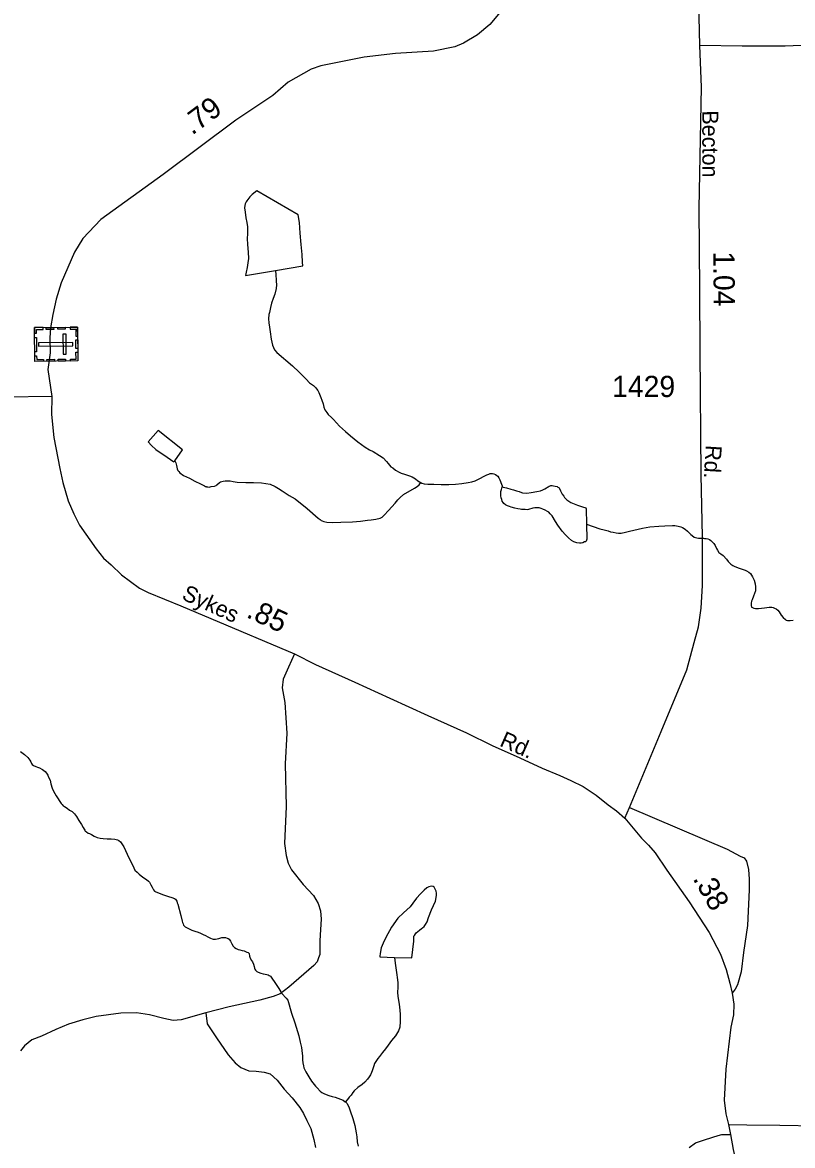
# Model space of a CAD drawing. Extents: x 2220236 to 2384410, y 720751 to 894131.
# Drawn here: x 2288550 to 2293089, y 826230 to 832849 of the extents above; entities that cross this region are included whole.
import ezdxf

# ---------------------------------------------------------------- set-up
doc = ezdxf.new("R2010")
doc.units = 0
for name, color, linetype in [('Exist Cultural Cemetery CELL', 7, 'Continuous'), ('Exist Hydrographic Creek Single Shore', 7, 'Continuous'), ('Exist Hydrographic Misc Water Feature', 7, 'Continuous'), ('Exist Hydrographic Pond Under 1500 Sq Ft', 7, 'Continuous'), ('Exist Road Non-System Type 51', 7, 'Continuous'), ('Exist Road Secondary Mileage Hundredths English Label', 7, 'Continuous'), ('Exist Road Secondary Type 51 Attributed', 7, 'Continuous'), ('Exist Road Secondary Type 51 Label', 7, 'Continuous'), ('Exist Road Secondary Type 51 Number Label', 7, 'Continuous')]:
    doc.layers.add(name, color=color, linetype=linetype)

msp = doc.modelspace()

# ---------------------------------------------------------------- linework, layer by layer
at = {"layer": 'Exist Cultural Cemetery CELL'}
for points in [[(2288875.5, 831053.2), (2288877.3, 830854.1), (2288622.7, 830851.8), (2288620.8, 831050.9)], [(2288621.2, 831017.8), (2288632.7, 831017.9), (2288632.5, 831039.9), (2288672.9, 831040.3), (2288672.8, 831051.4), (2288620.9, 831050.9)], [(2288690.8, 831051.6), (2288734.1, 831052), (2288734.2, 831040.6), (2288690.9, 831040.2)], [(2288758, 831052.2), (2288801.3, 831052.6), (2288801.4, 831041.2), (2288758.1, 831040.8)], [(2288807.8, 831011.8), (2288789.1, 831011.6), (2288790.2, 830893.9), (2288808.8, 830894)], [(2288832.1, 831052.8), (2288832.2, 831041.5), (2288864.4, 831041.8), (2288864.8, 831001.2), (2288875.9, 831001.3), (2288875.5, 831053.2)], [(2288632.8, 830993.5), (2288633.6, 830908.7), (2288622.2, 830908.6), (2288621.4, 830993.4)], [(2288847.1, 830943.9), (2288847, 830962.6), (2288644.2, 830960.8), (2288644.4, 830942.1)], [(2288876.1, 830979.1), (2288876.6, 830927.3), (2288865.2, 830927.2), (2288864.7, 830979)], [(2288622.3, 830884.9), (2288633.8, 830885), (2288634, 830863), (2288674.4, 830863.4), (2288674.5, 830852.3), (2288622.7, 830851.8)], [(2288833.9, 830853.7), (2288833.8, 830865), (2288866, 830865.3), (2288865.6, 830905.9), (2288876.7, 830906), (2288877.2, 830854.1)], [(2288694.8, 830863.8), (2288738.1, 830864.2), (2288738.2, 830852.8), (2288694.9, 830852.5)], [(2288760.7, 830864.4), (2288804, 830864.8), (2288804.1, 830853.4), (2288760.8, 830853)]]:
    msp.add_lwpolyline(points, close=True, dxfattribs=at)
at = {"layer": 'Exist Hydrographic Creek Single Shore'}
for points in [[(2288539.1, 828552.5), (2288561.4, 828535), (2288581.3, 828517.2), (2288593.8, 828501.5), (2288599.5, 828491.6), (2288603.9, 828481.6), (2288607.4, 828476.6), (2288615.8, 828469.9), (2288629.8, 828463.7), (2288639.8, 828459.6), (2288649.9, 828456.1), (2288664.2, 828447.6), (2288668.1, 828445.9), (2288676.2, 828439.8), (2288684.2, 828434), (2288692.2, 828424), (2288700.2, 828412.4), (2288704.6, 828401.5), (2288712.7, 828382.6), (2288716.9, 828361.9), (2288725.2, 828336.4), (2288733.3, 828318.2), (2288749.5, 828290.7), (2288777.8, 828246.8), (2288783.5, 828239.1), (2288789.9, 828232.4), (2288798, 828227.4), (2288813.3, 828218.2), (2288828.1, 828207.1), (2288842.4, 828197.9), (2288856.2, 828184.5), (2288868.3, 828169.5), (2288882.6, 828146.2), (2288897.9, 828122), (2288907.7, 828104.7), (2288913.3, 828093.8), (2288917.2, 828088.1), (2288920.3, 828083.8), (2288922, 828082.1), (2288927.4, 828078.1), (2288937.5, 828071.9), (2288945.3, 828068.5), (2288957.6, 828062.7), (2288972.2, 828054.2), (2288989.8, 828046.3), (2289007.7, 828042.6), (2289025.7, 828040.6), (2289049.3, 828037.8), (2289073.5, 828037.3), (2289094.8, 828035.2), (2289109.5, 828031.6), (2289119.2, 828027.2), (2289127.6, 828019.8), (2289148, 827990.5), (2289176.5, 827926), (2289192.9, 827896.1), (2289207.1, 827866.3), (2289213, 827853), (2289225.3, 827840.7), (2289237.5, 827828.9), (2289259.4, 827811.1), (2289281.8, 827797.5), (2289293.7, 827789.1), (2289299.8, 827781.7), (2289306, 827765.8)], [(2289306, 827765.8), (2289313.9, 827751.9), (2289322.2, 827737.6), (2289328.2, 827729.3), (2289336.4, 827725.9), (2289352.3, 827719.9), (2289376.4, 827710.3), (2289416.8, 827696.3), (2289424.6, 827694.5), (2289430.8, 827692.7), (2289446.7, 827686.8), (2289452.5, 827682.4), (2289460.5, 827670.8), (2289462.9, 827660.9), (2289465, 827652.7), (2289483.4, 827586.7), (2289491.8, 827553.1), (2289494, 827545.5), (2289496.4, 827536.6), (2289499.9, 827529), (2289509.2, 827518.9), (2289524.1, 827511.4), (2289548.1, 827499.4), (2289566.4, 827494.1), (2289584.9, 827487.8), (2289600.2, 827481.9), (2289614.5, 827474.1), (2289628.5, 827468.2), (2289642.4, 827460.4), (2289658.7, 827452.8), (2289668.4, 827448.4), (2289674.6, 827446.6), (2289680.5, 827446.5), (2289688.7, 827447.3), (2289706.8, 827450.9), (2289724.7, 827455.4), (2289735.5, 827456.2), (2289746.6, 827455.9), (2289756.7, 827453.1), (2289763.2, 827449.7), (2289768.7, 827445.6), (2289772.9, 827440.6), (2289776.7, 827434), (2289784.9, 827418.1), (2289792.8, 827404.2), (2289799.2, 827398.1), (2289809.9, 827390.7), (2289821.3, 827386.2), (2289831.1, 827384.3), (2289845.1, 827380.1), (2289857.2, 827376.6), (2289873.1, 827370.3), (2289879.6, 827368.6), (2289885.4, 827361.2), (2289887.4, 827346.4), (2289891.7, 827334.9), (2289899.6, 827320.6), (2289905.7, 827313.3), (2289912, 827299), (2289915.9, 827285.2), (2289918, 827275.3), (2289920.2, 827268.7), (2289922.7, 827264.4), (2289926.3, 827261), (2289931.7, 827256), (2289936.3, 827253.6), (2289948.3, 827247.4), (2289954.5, 827245), (2289967.9, 827242.1), (2289980.3, 827239.6), (2289990.4, 827237.7), (2289998.6, 827235.9), (2290005, 827232.5), (2290011.2, 827228.1), (2290016.6, 827221.4), (2290040.8, 827185.8), (2290061.2, 827156.5), (2290079.6, 827126.6), (2290103.6, 827098.3), (2290113.9, 827085.9), (2290136.6, 827010.7), (2290155, 826952.9), (2290179.7, 826876.9), (2290187.8, 826839), (2290194.3, 826807.7), (2290198.6, 826773.2), (2290200.9, 826757.8), (2290201, 826735.5), (2290203.3, 826717.4), (2290207.2, 826699.2), (2290209.2, 826687.7), (2290219.6, 826663.9), (2290237.6, 826634), (2290253.9, 826609.7), (2290278.2, 826579.7), (2290286.5, 826569.7), (2290304.5, 826550.6)], [(2290304.5, 826550.6), (2290314.5, 826542.2), (2290326.8, 826536.1), (2290340.5, 826530.9), (2290356.7, 826524.9), (2290374.7, 826518.7), (2290393.9, 826514.3), (2290408.9, 826509.1), (2290424.9, 826503.8), (2290440.1, 826497), (2290452.7, 826487.5), (2290453.7, 826486.9)], [(2290453.7, 826486.9), (2290461.1, 826480.1), (2290473.1, 826457.6), (2290481.5, 826433.8), (2290497.9, 826389.8), (2290508.2, 826348), (2290516.8, 826305.8), (2290520.9, 826280.5), (2290523.3, 826252.5), (2290529.3, 826226.2)]]:
    msp.add_lwpolyline(points, dxfattribs=at)
at = {"layer": 'Exist Hydrographic Misc Water Feature'}
for points in [[(2290040.7, 831387.3), (2290042.8, 831362.7), (2290043.9, 831353.5), (2290045.2, 831338.7), (2290046.2, 831323.9), (2290046.5, 831302.6), (2290045.7, 831281.3), (2290037.1, 831247), (2290028.1, 831222.6), (2290018.7, 831195.9), (2290012.5, 831168.8), (2290007, 831140.4), (2290003.2, 831129), (2290000, 831101.8), (2290001.8, 831078.8), (2290005.6, 831054.2), (2290009.9, 831026.2), (2290016.2, 830982.8), (2290024.6, 830946.5), (2290035.6, 830920.7), (2290049, 830905), (2290141.5, 830826), (2290180.4, 830787.5), (2290204.5, 830764), (2290222.2, 830746.3), (2290242.8, 830726.2), (2290264.7, 830708.7), (2290276.6, 830697.6), (2290283, 830690.9), (2290291, 830679.3), (2290297.4, 830669.3), (2290309.2, 830638.9), (2290315.4, 830623), (2290321.5, 830601.6), (2290326, 830581.1), (2290332.3, 830566.9), (2290344.1, 830549.6), (2290352.1, 830539.6), (2290372.4, 830521.8), (2290382.6, 830510.1), (2290400.6, 830490), (2290418.8, 830470), (2290453.3, 830438.1), (2290483.3, 830412.9), (2290525.8, 830376.9), (2290569.8, 830345.5), (2290595.4, 830331.2), (2290618.1, 830319.9), (2290654.4, 830297.8), (2290676.4, 830282.6), (2290696.6, 830262.5), (2290704.6, 830250.9), (2290712.9, 830240.9), (2290721.5, 830230.8), (2290732.9, 830223.4), (2290749, 830211.6), (2290769.7, 830198.7), (2290783.1, 830193.5), (2290801, 830187.5), (2290831.6, 830177.7), (2290847.2, 830171.8), (2290867.3, 830159.9), (2290880.9, 830148.2), (2290889.6, 830142.1), (2290898.7, 830137)], [(2289448, 830265.4), (2289453.4, 830253.2), (2289457.3, 830239), (2289459.7, 830227.5), (2289461.5, 830218.6), (2289465.6, 830209.3), (2289471, 830202), (2289477.7, 830195.3), (2289500.1, 830180.1), (2289534.2, 830163.6), (2289565.9, 830146.6), (2289600.4, 830130.4), (2289614.3, 830122.6), (2289622.4, 830119.1), (2289628.3, 830115.1), (2289632.5, 830113.4), (2289635.7, 830111.7), (2289642.3, 830111.5), (2289651.1, 830111.3), (2289662.3, 830113.4), (2289682.4, 830117.2), (2289691, 830120.3), (2289696.3, 830123.5), (2289712.4, 830137.9), (2289717.7, 830141.1), (2289732.2, 830145.7), (2289744.1, 830147.8), (2289750.3, 830147.7), (2289774.2, 830148.1), (2289792.2, 830144.5), (2289816.1, 830140.7), (2289866.2, 830137.1), (2289912.1, 830137.7), (2289958.3, 830136.1), (2290010, 830128.5), (2290040.2, 830114.8), (2290058.3, 830102.9), (2290080.3, 830089.3), (2290122.7, 830061.2), (2290156.8, 830041.8), (2290227.4, 829984.6), (2290293.8, 829928.1), (2290303.8, 829919.1), (2290309.9, 829914.7), (2290316.1, 829911.3), (2290325.8, 829907.1), (2290344.1, 829903.5), (2290376.2, 829901.8), (2290425.8, 829904.1), (2290495.7, 829906.9), (2290542.7, 829910.8), (2290583.8, 829915.5), (2290604.8, 829917.7), (2290632.5, 829922.7), (2290657.5, 829928.1), (2290662.8, 829929.6), (2290669.5, 829934.4), (2290681.2, 829944.7), (2290707, 829973), (2290746.9, 830017.1), (2290762.7, 830034.8), (2290776.5, 830049.3), (2290796.5, 830067.9), (2290859.9, 830104.3), (2290875.9, 830114.5), (2290888.2, 830125), (2290898.7, 830137)], [(2290898.7, 830137), (2290903.5, 830134.6), (2290916.9, 830130), (2290939.8, 830127.3), (2290975.5, 830127.2), (2291017.5, 830125.6), (2291063.7, 830126.3), (2291101.5, 830127.8), (2291139.6, 830133), (2291177.8, 830138.7), (2291197.9, 830142.2), (2291217.4, 830147.7), (2291245.2, 830161.9), (2291271.1, 830176.1), (2291287, 830184), (2291298.9, 830187.7), (2291306.5, 830190.2), (2291313.4, 830190.7), (2291320.9, 830190.5), (2291329.1, 830188.7), (2291338.5, 830185.2), (2291346.9, 830180.1), (2291351.1, 830176.1), (2291356.8, 830166.2), (2291363.1, 830154.6), (2291373.4, 830128.8), (2291376.5, 830118.2), (2291377.7, 830113.3)], [(2291874.6, 829891.4), (2291953.7, 829865.8), (2291977.8, 829858.1), (2292001.7, 829852.7), (2292015.7, 829848.1), (2292031.7, 829844.5), (2292049.6, 829840.9), (2292063.7, 829838.9), (2292079.5, 829839.6), (2292103.9, 829845.7), (2292127.6, 829851.7), (2292205.3, 829868.1), (2292247.5, 829877.1), (2292301.4, 829880.9), (2292335.2, 829883.5), (2292380.5, 829884.9), (2292395.2, 829883.9), (2292415.2, 829880.2), (2292431.2, 829876.6), (2292439.3, 829872.2), (2292456.4, 829862), (2292469.3, 829850.2), (2292479.6, 829841.1), (2292489.3, 829831.8), (2292497.7, 829825), (2292509.6, 829816.6), (2292516.1, 829814.1), (2292523.9, 829811.4), (2292533.7, 829809.5), (2292545.9, 829809.3), (2292563.9, 829809.9), (2292570.8, 829808.8), (2292576, 829808), (2292580, 829807.9), (2292588.8, 829805.1), (2292599.8, 829801.6), (2292607.9, 829795.8), (2292616, 829788.1), (2292624.3, 829778.1), (2292632.2, 829765.8), (2292640.4, 829749.9), (2292646.4, 829738.3), (2292654.4, 829726), (2292666.6, 829716.6), (2292679.9, 829707.4), (2292699.1, 829686.4), (2292709, 829673), (2292725.1, 829657.3), (2292736.4, 829649.5), (2292749.4, 829642.7), (2292773.5, 829633.3), (2292791.4, 829627.1), (2292809.3, 829621.8), (2292817.4, 829617.7), (2292831.3, 829609.8), (2292841.3, 829601.4), (2292853.7, 829582.5), (2292861.9, 829562.6), (2292868.3, 829540.2), (2292871.2, 829522.1), (2292871.3, 829510), (2292870.4, 829500.1), (2292864.8, 829483.9), (2292858.6, 829468.2), (2292849.9, 829447.1), (2292847.1, 829438.3), (2292844.9, 829425.9), (2292844.7, 829417), (2292845.3, 829410.5), (2292846.1, 829406.2), (2292847.4, 829403.9), (2292852.9, 829401.1), (2292861.4, 829397.7), (2292871.2, 829395.8), (2292888.9, 829395.5), (2292905.3, 829396.8), (2292923.4, 829399), (2292937.9, 829401), (2292951.4, 829402.4), (2292967.4, 829403), (2292975.3, 829401.2), (2292982.7, 829397.8), (2292991.5, 829393.3), (2293001.5, 829385.9), (2293009.5, 829375.9), (2293021.6, 829356.6), (2293034.1, 829341.6), (2293047.9, 829329.8), (2293051.5, 829327.5), (2293058.3, 829324), (2293061.9, 829324), (2293075.7, 829324.3), (2293091.8, 829326.6)], [(2290743.3, 827339.2), (2290747.5, 827304.7), (2290756.2, 827236.6), (2290758.2, 827220.8), (2290762.5, 827190.5), (2290762.5, 827161), (2290761, 827134.8), (2290763.1, 827108.5), (2290769.3, 827074.6), (2290771.7, 827048.3), (2290776, 827004.9), (2290776.7, 826960.7), (2290775, 826926.9), (2290767.1, 826905.1), (2290748.4, 826876), (2290725.9, 826848.6), (2290706, 826821.7), (2290690.1, 826800.1), (2290672.2, 826777.5), (2290654.4, 826755.6), (2290644.7, 826743.6), (2290632.5, 826725.9), (2290625, 826713.5), (2290621.1, 826698.9), (2290611.3, 826671.2), (2290607.5, 826661.4), (2290601.3, 826646.8), (2290593.5, 826634.8), (2290583.7, 826620.9), (2290567.9, 826602.6), (2290552.2, 826588.8), (2290526, 826572.3), (2290504.2, 826552.1), (2290496.5, 826542.4), (2290486.7, 826527.8), (2290476.6, 826515.9), (2290470.9, 826510.1), (2290453.7, 826486.9)]]:
    msp.add_lwpolyline(points, dxfattribs=at)
at = {"layer": 'Exist Hydrographic Pond Under 1500 Sq Ft'}
for points in [[(2290040.7, 831387.3), (2290202.3, 831414.2), (2290200.1, 831436.5), (2290197.8, 831482.5), (2290193.1, 831540.6), (2290186.6, 831608), (2290182, 831670.4), (2290175.7, 831716.5), (2289932.4, 831857.6), (2289904.7, 831836.2), (2289890.9, 831821.7), (2289878.8, 831805.6), (2289873.1, 831797.5), (2289869, 831791.7), (2289863.2, 831779.7), (2289860, 831769.9), (2289859.4, 831757.4), (2289861.8, 831731.2), (2289866.1, 831697.6), (2289872.1, 831671.3), (2289875.8, 831644), (2289876.6, 831622), (2289876.9, 831603.9), (2289875, 831575.1), (2289877.5, 831539.9), (2289881.2, 831495.6), (2289882.1, 831457.9), (2289878.6, 831431.7), (2289874.8, 831405.5), (2289868, 831378.4), (2289865.3, 831358.2), (2290040.7, 831387.3)], [(2289448, 830265.4), (2289492.7, 830330.1), (2289349.7, 830444.6), (2289292, 830377.9), (2289310.5, 830356.2), (2289336.6, 830332.7), (2289403.2, 830287), (2289443, 830259), (2289448, 830265.4)], [(2291874.6, 829891.4), (2291876, 829803.5), (2291872.5, 829793.1), (2291868.5, 829788.9), (2291862.6, 829787.4), (2291852.3, 829782.6), (2291842.4, 829781.2), (2291833.2, 829779.8), (2291817.5, 829781.7), (2291799.9, 829788), (2291786.3, 829796.5), (2291768, 829812.3), (2291751.3, 829830), (2291731.7, 829851.7), (2291705.6, 829887.4), (2291691.2, 829907.3), (2291671.3, 829941.5), (2291660.7, 829953.9), (2291652, 829962.3), (2291644.9, 829967.3), (2291630.6, 829975.2), (2291617.6, 829981), (2291606.6, 829984.5), (2291595.5, 829988), (2291582.1, 829989.3), (2291570.9, 829988.6), (2291558.7, 829986.5), (2291533, 829977.9), (2291525.4, 829977.4), (2291513, 829978.3), (2291501.5, 829978.5), (2291491, 829979.7), (2291482.8, 829980.5), (2291468.8, 829983.5), (2291452.5, 829987.1), (2291430.6, 829993.1), (2291420.2, 829996.6), (2291408.5, 830001.1), (2291396.5, 830006.9), (2291386.5, 830014.7), (2291382.6, 830020.3), (2291378.2, 830028.6), (2291375.1, 830037.9), (2291372.1, 830048.4), (2291370.3, 830059.3), (2291369, 830074.1), (2291370.2, 830085.5), (2291373.4, 830096.9), (2291377.7, 830113.3)], [(2291377.7, 830113.3), (2291383.5, 830110.5), (2291403.5, 830106.8), (2291427.6, 830099.1), (2291443.5, 830093.9), (2291461.8, 830089.2), (2291477.8, 830084), (2291492.1, 830079.7), (2291498, 830078), (2291521.9, 830075.8), (2291547.8, 830078.6), (2291581.7, 830084.4), (2291603.8, 830088.9), (2291617.4, 830094.2), (2291629.7, 830101.5), (2291639.6, 830106.8), (2291645.3, 830111), (2291648.6, 830112.6), (2291653.6, 830115.7), (2291661.2, 830118.9), (2291663.5, 830119.5), (2291671.3, 830119.3), (2291680.2, 830119.1), (2291690.3, 830116.6), (2291701.4, 830113.8), (2291705.9, 830111.4), (2291710.8, 830108.6), (2291712.4, 830107), (2291713.7, 830106.3), (2291721.9, 830088.1), (2291731.7, 830069.8), (2291739.9, 830056.5), (2291745, 830048.9), (2291750.5, 830043.2), (2291758.8, 830035.5), (2291769.8, 830028.1), (2291782.1, 830020.3), (2291820.5, 830004.7), (2291850.5, 829995.2), (2291870.4, 829988.9), (2291872.5, 829983.3), (2291874.6, 829891.4)], [(2290743.3, 827339.2), (2290845.2, 827335.4), (2290856.1, 827433.6), (2290856.3, 827445.1), (2290855.9, 827457.6), (2290857.7, 827463.1), (2290860, 827467.3), (2290865.8, 827477.7), (2290871.5, 827483.5), (2290879.6, 827491.5), (2290889.6, 827500.1), (2290901.3, 827509.7), (2290907.6, 827513.9), (2290916.9, 827521.9), (2290925.3, 827532.2), (2290935.2, 827548.4), (2290943, 827574.5), (2290960.6, 827620), (2290984, 827670.4), (2290988, 827691), (2290989.6, 827704.7), (2290989.9, 827717.2), (2290987.5, 827728.7), (2290985.3, 827736.9), (2290981.3, 827745.2), (2290977.1, 827752.5), (2290971, 827756.9), (2290959.2, 827758.8), (2290945.4, 827754.2), (2290933.4, 827748.5), (2290917.1, 827735.7), (2290895.7, 827714.2), (2290871.8, 827687.5), (2290850.3, 827659.4), (2290834.4, 827637.4), (2290796.6, 827601.5), (2290762.8, 827571), (2290725.6, 827516.7), (2290692.2, 827456), (2290676.4, 827421.9), (2290664.7, 827394.3), (2290658.8, 827361.6), (2290657.1, 827345.9), (2290657.1, 827342), (2290743.3, 827339.2)]]:
    msp.add_lwpolyline(points, dxfattribs=at)
at = {"layer": 'Exist Road Non-System Type 51'}
for points in [[(2293279.6, 832719), (2293044.3, 832710.2), (2292791.4, 832710.2), (2292542.1, 832713.7)], [(2290153.9, 829128.9), (2290118.9, 829050.1), (2290087.4, 828978.3), (2290080.4, 828927.5), (2290096.1, 828841.7), (2290108.4, 828661.4), (2290097.9, 828479.3), (2290104.9, 828228.9), (2290094.4, 828010), (2290104.9, 827940), (2290117.1, 827894.4), (2290136.4, 827854.2), (2290204.6, 827768.4), (2290265.9, 827703.6), (2290293.9, 827656.3), (2290306.1, 827612.5), (2290311.4, 827563.5), (2290306.1, 827504), (2290302.6, 827437.4), (2290302.6, 827377.9), (2290302.6, 827356.9), (2290295.6, 827335.9), (2290286.9, 827313.1), (2290267.6, 827292.1), (2290119.7, 827162.5), (2290069, 827124), (2290027, 827108.2), (2289948.3, 827087.2), (2289768, 827047), (2289631.5, 827011.9)], [(2292127.7, 828222.7), (2292703.6, 827976.7), (2292780.9, 827936.3), (2292803.7, 827925.8), (2292817.8, 827906.4), (2292828.3, 827857.2), (2292833.6, 827799.3), (2292833.6, 827737.8), (2292823.9, 827526.9), (2292800.2, 827367), (2292786.1, 827254.6), (2292765.1, 827177.3), (2292751, 827150.9), (2292733.5, 827128.1)], [(2289631.5, 827011.9), (2289485.8, 826971), (2289437.9, 826966.6), (2289383.8, 826977.9), (2289299.7, 827001.2), (2289221.5, 827012.5), (2289129.7, 827009.6), (2288983.9, 826990.2), (2288906.2, 826971.4), (2288822.4, 826944.8), (2288746.6, 826913.9), (2288663, 826875.3), (2288605.4, 826852.7), (2288561.7, 826818.4), (2288538.1, 826788.1)], [(2289631.5, 827011.9), (2289638.5, 826947.2), (2289694.5, 826864.9), (2289762.8, 826765.1), (2289804.8, 826717.8), (2289838, 826689.8), (2289885.3, 826670.5), (2289927.3, 826668.8), (2289974.5, 826661.7), (2290009.5, 826653), (2290051.5, 826616.2), (2290093.5, 826561.9), (2290140.7, 826511.2), (2290184.5, 826455.1), (2290207.2, 826418.4), (2290226.5, 826378.1), (2290249.2, 826330.8), (2290266.7, 826266), (2290277.2, 826218.7)], [(2292480.3, 826218.7), (2292517.1, 826245), (2292563.4, 826262.5), (2292619.4, 826280), (2292650.9, 826288.8), (2292671.9, 826295.8), (2292696.4, 826295.8), (2292722.9, 826294.1)]]:
    msp.add_lwpolyline(points, dxfattribs=at)
at = {"layer": 'Exist Road Secondary Type 51 Attributed'}
for points in [[(2292099.6, 828159.4), (2292127.7, 828222.7), (2292314.7, 828670.7), (2292465.7, 829034.5), (2292509.6, 829194.3), (2292534.2, 829287.5), (2292550, 829398.2), (2292558.8, 829529.9), (2292558.8, 829818.1), (2292550, 830183.6), (2292544.7, 830909.2), (2292543, 831272.9), (2292538.6, 831754.4), (2292551.7, 832467.7), (2292542.1, 832713.7), (2292533.3, 833135.4), (2292528, 833486.8), (2292522.8, 833574.7)], [(2291365.3, 832910.2), (2291304, 832837.6), (2291232.5, 832776.9), (2291149, 832728.3), (2291099.3, 832705.7), (2290973.6, 832680.5), (2290747.8, 832666.4), (2290564.2, 832644.9), (2290308.6, 832594.4), (2290250.8, 832574), (2290115.6, 832496.6), (2290026.4, 832419.9), (2289807.9, 832273.8), (2289379.1, 831954), (2289011.7, 831688.5), (2288906.8, 831575.7), (2288857.5, 831495.2), (2288777.4, 831314.5), (2288748.2, 831218.3), (2288729.2, 831128.1), (2288715.9, 831050), (2288712.5, 830990.1), (2288713.3, 830902.1), (2288700.2, 830804), (2288722.5, 830645.8)], [(2288722.5, 830645.8), (2288166.6, 830636.5), (2287886.3, 830636.5), (2287733.4, 830634.2), (2287668.5, 830622.6), (2287615.3, 830608.7), (2287527.2, 830569.3), (2287464.7, 830529.9), (2287392.9, 830471.9), (2287212.2, 830293.5), (2287021.1, 830132.4), (2286932, 830065.7), (2286522.9, 829770), (2286284.5, 829603.8), (2286114.3, 829486.9), (2285938.2, 829361.7)], [(2288722.5, 830645.8), (2288720.7, 830538.2), (2288735.9, 830402.5), (2288769.7, 830220.9), (2288788.4, 830137.1), (2288819.3, 830029.5), (2288852.1, 829953.8), (2288886.7, 829886.1), (2288984, 829747.1), (2289028.4, 829691.6), (2289072.8, 829651.9), (2289133.4, 829594.5), (2289240.1, 829515.7), (2289290.2, 829490), (2289482.9, 829411.9), (2289659.5, 829335.6), (2290153.9, 829128.9), (2290276.4, 829065.8), (2290509.1, 828960.8), (2290715.6, 828866.2), (2290939.6, 828764.7), (2291167, 828663.1), (2291317.5, 828587.8), (2291482, 828514.3), (2291613.3, 828454.7), (2291716.8, 828410.7), (2291783, 828381.2), (2291855.5, 828345.7), (2291931, 828294.7), (2292003, 828238.5), (2292050.4, 828203.4), (2292099.6, 828159.4)], [(2292099.6, 828159.4), (2292198.5, 828042), (2292239.1, 828000.4), (2292279.3, 827954.7), (2292348.4, 827853.5), (2292479.7, 827665.7), (2292597.4, 827484.7), (2292664.1, 827358.2), (2292698.4, 827266.9), (2292719.4, 827187.8), (2292733.5, 827128.1), (2292743.5, 827063.5), (2292740.1, 826999.6), (2292724.8, 826927.3), (2292695.1, 826679.2), (2292685.2, 826497.3), (2292695.7, 826416.5), (2292711.5, 826353.2)], [(2292711.5, 826353.2), (2292722.9, 826294.1), (2292739.6, 826207.4), (2292776.5, 826040.4), (2292818.6, 825857.7), (2292859, 825675), (2292895.9, 825502.8), (2292960.9, 825218.1), (2293018.8, 824972.2), (2293058.3, 824845.5), (2293107.7, 824691.9), (2293146.5, 824598.4), (2293193.4, 824494.9), (2293220.7, 824441.5), (2293271.7, 824302.7), (2293303.3, 824172.7), (2293320.8, 824025.1), (2293325.2, 823814.3), (2293321.7, 823594.6), (2293323.5, 823339.9), (2293326.1, 823014.8), (2293327.9, 822612.4)], [(2292711.5, 826353.2), (2292818.6, 826351.4), (2293013.5, 826349.7), (2293231.3, 826346.2)]]:
    msp.add_lwpolyline(points, dxfattribs=at)

# ---------------------------------------------------------------- texts
at = {"layer": 'Exist Road Secondary Mileage Hundredths English Label'}
for s, rotation, p in [('.79', 36.71598, (2289550.2, 832182.2)), ('1.04', 270.53, (2292621.4, 831500.1)), ('.85', 335.40976, (2289863.7, 829346)), ('.38', 299.84786, (2292498.4, 827803.4))]:
    msp.add_text(s, height=125, rotation=rotation, dxfattribs=at).set_placement(p)
at = {"layer": 'Exist Road Secondary Type 51 Label'}
for s, rotation, p in [('Becton', 270.23443, (2292556.1, 832331)), ('Rd.', 266.55058, (2292577.5, 830360.4)), ('Sykes', 335.40976, (2289483.1, 829452.4)), ('Rd.', 336.16011, (2291357, 828587.7))]:
    msp.add_text(s, height=95, rotation=rotation, dxfattribs=at).set_placement(p)
at = {"layer": 'Exist Road Secondary Type 51 Number Label'}
msp.add_text('1429', height=125, dxfattribs=at).set_placement((2292025.3, 830641.7))

doc.saveas('drawing.dxf')
